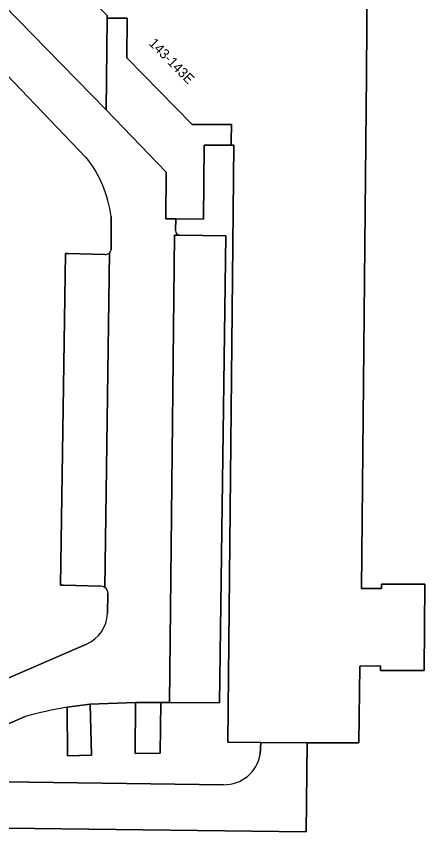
# Model space of a CAD drawing. Extents: x 159262 to 160143, y 383399 to 384319.
# Drawn here: x 159405.7 to 159447, y 383522.6 to 383605 of the extents above; entities that cross this region are included whole.
import ezdxf

# ---------------------------------------------------------------- set-up
doc = ezdxf.new("R2010")
doc.units = 0
for name, color, linetype in [('IMGEO_Erf', 7, 'Continuous'), ('IMGEO_Pand', 7, 'Continuous'), ('IMGEO_Pand_nummerreeks', 7, 'Continuous'), ('IMGEO_Parkeervlak_open', 7, 'Continuous'), ('IMGEO_Rijbaan_lokaal_gesloten', 7, 'Continuous'), ('IMGEO_Rijbaan_lokaal_open', 7, 'Continuous')]:
    doc.layers.add(name, color=color, linetype=linetype)

msp = doc.modelspace()

# ---------------------------------------------------------------- linework, layer by layer
at = {"layer": 'IMGEO_Erf'}
for points in [[(159396.115, 383607.307), (159402.842, 383607.797), (159414.793, 383595.541), (159414.911, 383604.832), (159414.914, 383605.09), (159377.744, 383643.002)], [(159441.25, 383614.012), (159441.121, 383599.115), (159440.619, 383547.18), (159442.655, 383547.178), (159442.643, 383547.602), (159447.024, 383547.601), (159446.962, 383538.883), (159442.56, 383538.888), (159442.547, 383539.346), (159440.449, 383539.323), (159440.361, 383531.572), (159435.135, 383531.595), (159435.025, 383522.598), (159402.024, 383522.999), (159402.028, 383523.401), (159395.337, 383523.526), (159394.706, 383523.853), (159389.98, 383523.831)], [(159412.799, 383590.722), (159401.713, 383602.231)], [(159427.729, 383591.98), (159427.441, 383591.978), (159424.732, 383591.999), (159424.66, 383584.514), (159421.85, 383584.543), (159421.818, 383583.351)], [(159430.37, 383530.422), (159430.462, 383531.615), (159427.108, 383531.63), (159427.729, 383591.98)], [(159415.309, 383581.452), (159415.3, 383584.773)], [(159422.259, 383582.874), (159426.921, 383582.814), (159426.287, 383535.61), (159421.218, 383535.662), (159420.353, 383535.672), (159420.275, 383530.52), (159417.739, 383530.485), (159417.792, 383535.666), (159413.205, 383535.491), (159413.338, 383530.322), (159410.9, 383530.252), (159410.856, 383535.17)], [(159414.187, 383547.403), (159410.501, 383547.502), (159410.179, 383547.511), (159410.68, 383581.04)], [(159410.68, 383581.04), (159410.94, 383581.034), (159414.664, 383580.942)], [(159414.952, 383544.659), (159414.983, 383546.67)], [(159398.629, 383544.874), (159394.249, 383535.129), (159393.253, 383533.085), (159412.828, 383541.541)], [(159406.606, 383534.23), (159397.925, 383530.461), (159397.555, 383530.015), (159397.358, 383527.762)], [(159398.096, 383526.973), (159402.114, 383526.914), (159402.109, 383527.655), (159426.68, 383527.347)]]:
    msp.add_lwpolyline(points, dxfattribs=at)
msp.add_lwpolyline([(159427.441, 383591.978), (159427.447, 383592.397), (159427.472, 383594.058), (159423.521, 383594.064), (159416.904, 383600.8), (159416.932, 383604.808), (159415.318, 383604.827), (159414.911, 383604.832), (159414.793, 383595.541), (159420.874, 383589.259), (159420.838, 383584.554), (159421.85, 383584.543), (159424.66, 383584.514), (159424.732, 383591.999)], close=True, dxfattribs=at)
for centre, radius, start, end in [((159403.562, 383583.339), 11.825, 6.96751, 38.63692), ((159422.31, 383583.363), 0.492, 181.44866, 264.05986), ((159414.739, 383581.519), 0.574, 313.48803, 353.2506), ((159414.728, 383581.521), 0.582, 263.64755, 314.17057), ((159414.258, 383546.686), 0.72, 55.51949, 95.67744), ((159414.256, 383546.68), 0.727, 359.2255, 55.69378), ((159411.295, 383544.868), 3.663, 294.73806, 356.7361), ((159417.721, 383494.054), 41.685, 99.47894, 105.46445), ((159426.775, 383530.985), 3.639, 268.51182, 351.09932)]:
    msp.add_arc(centre, radius, start, end, dxfattribs=at)
at = {"layer": 'IMGEO_Pand'}
msp.add_lwpolyline([(159414.914, 383605.09), (159414.911, 383604.832), (159415.318, 383604.827), (159416.932, 383604.808), (159416.904, 383600.8), (159423.521, 383594.064), (159427.472, 383594.058), (159427.447, 383592.397), (159427.441, 383591.978), (159427.729, 383591.98), (159427.108, 383531.63), (159430.462, 383531.615), (159435.135, 383531.595), (159440.361, 383531.572), (159440.449, 383539.323), (159442.547, 383539.346), (159442.56, 383538.888), (159446.962, 383538.883), (159447.024, 383547.601), (159442.643, 383547.602), (159442.655, 383547.178), (159440.619, 383547.18), (159441.121, 383599.115), (159441.25, 383614.012)], dxfattribs=at)
at = {"layer": 'IMGEO_Parkeervlak_open'}
for points in [[(159426.921, 383582.814), (159422.259, 383582.874), (159421.705, 383582.889), (159421.218, 383535.662), (159426.287, 383535.61)], [(159413.205, 383535.491), (159410.856, 383535.17), (159410.9, 383530.252), (159413.338, 383530.322)], [(159420.353, 383535.672), (159417.792, 383535.666), (159417.739, 383530.485), (159420.275, 383530.52)]]:
    msp.add_lwpolyline(points, close=True, dxfattribs=at)
for points in [[(159414.664, 383580.942), (159410.94, 383581.034), (159410.68, 383581.04), (159410.179, 383547.511), (159410.501, 383547.502), (159414.187, 383547.403)], [(159414.666, 383547.28), (159415.134, 383581.103)]]:
    msp.add_lwpolyline(points, dxfattribs=at)
for centre, radius, start, end in [((159414.728, 383581.521), 0.582, 263.64755, 314.17057), ((159414.258, 383546.686), 0.72, 55.51949, 95.67744)]:
    msp.add_arc(centre, radius, start, end, dxfattribs=at)
at = {"layer": 'IMGEO_Rijbaan_lokaal_gesloten'}
msp.add_lwpolyline([(159426.68, 383527.347), (159402.109, 383527.655), (159402.114, 383526.914), (159402.028, 383523.401), (159402.024, 383522.999), (159435.025, 383522.598), (159435.135, 383531.595), (159430.462, 383531.615), (159430.37, 383530.422)], dxfattribs=at)
msp.add_arc((159426.775, 383530.985), 3.639, 268.51182, 351.09932, dxfattribs=at)
at = {"layer": 'IMGEO_Rijbaan_lokaal_open'}
for points in [[(159414.793, 383595.541), (159402.842, 383607.797), (159396.115, 383607.307), (159398.074, 383603.385)], [(159401.713, 383602.231), (159412.799, 383590.722)], [(159421.818, 383583.351), (159421.85, 383584.543), (159420.838, 383584.554), (159420.874, 383589.259), (159414.793, 383595.541)], [(159415.3, 383584.773), (159415.309, 383581.452)], [(159410.856, 383535.17), (159413.205, 383535.491), (159417.792, 383535.666), (159420.353, 383535.672), (159421.218, 383535.662), (159421.705, 383582.889), (159422.259, 383582.874)], [(159415.134, 383581.103), (159414.666, 383547.28)], [(159414.983, 383546.67), (159414.952, 383544.659)], [(159412.828, 383541.541), (159393.253, 383533.085), (159389.98, 383523.831), (159394.706, 383523.853), (159395.337, 383523.526), (159402.028, 383523.401), (159402.114, 383526.914), (159398.096, 383526.973)], [(159397.358, 383527.762), (159397.555, 383530.015), (159397.925, 383530.461), (159406.606, 383534.23)]]:
    msp.add_lwpolyline(points, dxfattribs=at)
for centre, radius, start, end in [((159403.562, 383583.339), 11.825, 6.96751, 38.63692), ((159422.31, 383583.363), 0.492, 181.44866, 264.05986), ((159414.739, 383581.519), 0.574, 313.48803, 353.2506), ((159414.256, 383546.68), 0.727, 359.2255, 55.69378), ((159411.295, 383544.868), 3.663, 294.73806, 356.7361), ((159417.721, 383494.054), 41.685, 99.47894, 105.46445)]:
    msp.add_arc(centre, radius, start, end, dxfattribs=at)

# ---------------------------------------------------------------- texts
at = {"layer": 'IMGEO_Pand_nummerreeks'}
msp.add_text('143-143E', height=1, rotation=314.4894, dxfattribs=at).set_placement((159419.054, 383602.207))

doc.saveas('drawing.dxf')
